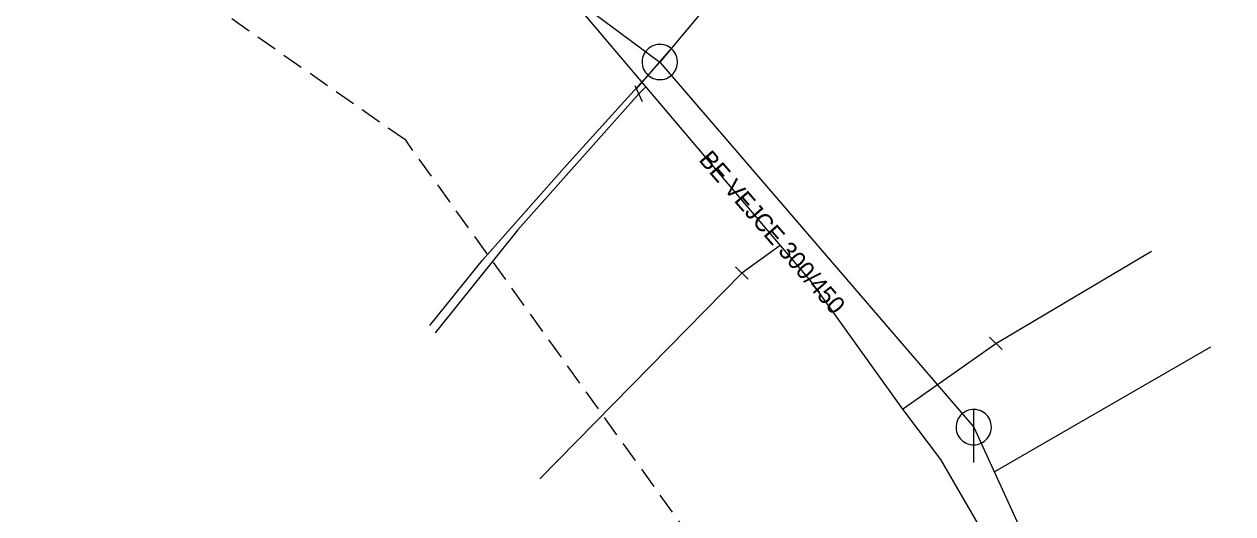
# Model space of a CAD drawing. Extents: x -749365 to -748625, y -965388 to -964881.
# Drawn here: x -748769.4 to -748701, y -965299.8 to -965272.1 of the extents above; entities that cross this region are included whole.
import ezdxf

# ---------------------------------------------------------------- set-up
doc = ezdxf.new("R2010")
doc.units = 0
doc.header["$LTSCALE"] = 0.4
doc.linetypes.add('MEDIUM_DASHED', pattern=[4.5, 3, -1.5])
for name, color, linetype, lineweight in [('1', 7, 'MEDIUM_DASHED', 25), ('11', 7, 'Continuous', 13), ('13', 7, 'Continuous', 13), ('14', 7, 'Continuous', 13), ('17', 7, 'Continuous', 25), ('22', 7, 'Continuous', 13), ('34', 7, 'Continuous', 13)]:
    doc.layers.add(name, color=color, linetype=linetype, lineweight=lineweight)

msp = doc.modelspace()

# ---------------------------------------------------------------- linework, layer by layer
at = {"layer": '1'}
msp.add_lwpolyline([(-748672.881, -965383.055), (-748747.771, -965278.626), (-748913.896, -965162.751)], dxfattribs=at)
at = {"layer": '11'}
for p, q in [((-748713.426, -965250.271), (-748733.398, -965274.196)), ((-748702.245, -965290.34), (-748714.473, -965297.398))]:
    msp.add_line(p, q, dxfattribs=at)
msp.add_lwpolyline([(-748746.413, -965289.099), (-748743.425, -965285.418), (-748738.662, -965280.008), (-748733.398, -965274.196)], dxfattribs=at)
at = {"layer": '13'}
for p, q in [((-748726.585, -965284.577), (-748728.763, -965286.143)), ((-748714.396, -965290.12), (-748705.592, -965284.897)), ((-748728.763, -965286.143), (-748740.183, -965297.786)), ((-748719.677, -965293.835), (-748714.396, -965290.12))]:
    msp.add_line(p, q, dxfattribs=at)
msp.add_lwpolyline([(-748734.588, -965275.991), (-748741.421, -965283.688), (-748746.104, -965289.53)], dxfattribs=at)
at = {"layer": '14', "lineweight": 25}
for p, q in [((-748733.398, -965274.196), (-748715.64, -965294.859)), ((-748715.64, -965294.859), (-748702.52, -965323.41))]:
    msp.add_line(p, q, dxfattribs=at)
at = {"layer": '14'}
msp.add_line((-748734.193, -965275.594), (-748734.588, -965275.991), dxfattribs=at)
at = {"layer": '14', "lineweight": 25}
msp.add_lwpolyline([(-748815.416, -965213.761), (-748783.169, -965237.598), (-748775.37, -965243.07), (-748733.398, -965274.196)], dxfattribs=at)
at = {"layer": '17'}
msp.add_lwpolyline([(-748738.234, -965270.822), (-748726.585, -965284.577), (-748724.84, -965286.638), (-748719.677, -965293.835), (-748717.51, -965296.688), (-748705.515, -965317.423), (-748697.278, -965331.659), (-748689.392, -965346.28), (-748687.454, -965349.21), (-748674.822, -965372.635), (-748674.485, -965375.898)], dxfattribs=at)
at = {"layer": '22'}
for p, q in [((-748734.708, -965275.707), (-748732.743, -965273.44)), ((-748715.64, -965296.859), (-748715.639, -965293.859))]:
    msp.add_line(p, q, dxfattribs=at)
for points in [[(-748732.642, -965274.851), (-748732.576, -965274.765), (-748732.518, -965274.671), (-748732.472, -965274.572), (-748732.436, -965274.469), (-748732.411, -965274.362), (-748732.399, -965274.253), (-748732.399, -965274.143), (-748732.411, -965274.035), (-748732.434, -965273.928), (-748732.469, -965273.824), (-748732.515, -965273.725), (-748732.573, -965273.631), (-748732.639, -965273.544), (-748732.715, -965273.465), (-748732.8, -965273.395), (-748732.89, -965273.335), (-748732.988, -965273.283), (-748733.09, -965273.244), (-748733.196, -965273.217), (-748733.303, -965273.2), (-748733.414, -965273.196), (-748733.522, -965273.204), (-748733.631, -965273.224), (-748733.735, -965273.254), (-748733.836, -965273.297), (-748733.931, -965273.35), (-748734.021, -965273.414), (-748734.102, -965273.487), (-748734.176, -965273.568), (-748734.24, -965273.657), (-748734.294, -965273.752), (-748734.337, -965273.853), (-748734.369, -965273.957), (-748734.39, -965274.065), (-748734.397, -965274.175), (-748734.394, -965274.284), (-748734.378, -965274.392), (-748734.351, -965274.498), (-748734.313, -965274.6), (-748734.262, -965274.698), (-748734.203, -965274.79), (-748734.133, -965274.874), (-748734.054, -965274.951), (-748733.968, -965275.018), (-748733.874, -965275.075), (-748733.776, -965275.122), (-748733.672, -965275.157), (-748733.565, -965275.182), (-748733.456, -965275.194), (-748733.347, -965275.195), (-748733.238, -965275.183), (-748733.131, -965275.159), (-748733.027, -965275.125), (-748732.928, -965275.078), (-748732.834, -965275.022), (-748732.747, -965274.955), (-748732.668, -965274.879)], [(-748714.64, -965294.859), (-748714.645, -965294.75), (-748714.663, -965294.642), (-748714.693, -965294.536), (-748714.733, -965294.435), (-748714.785, -965294.338), (-748714.847, -965294.248), (-748714.919, -965294.165), (-748714.999, -965294.091), (-748715.087, -965294.025), (-748715.181, -965293.97), (-748715.281, -965293.925), (-748715.386, -965293.892), (-748715.493, -965293.87), (-748715.602, -965293.86), (-748715.712, -965293.862), (-748715.82, -965293.876), (-748715.927, -965293.901), (-748716.03, -965293.938), (-748716.128, -965293.987), (-748716.22, -965294.045), (-748716.306, -965294.114), (-748716.383, -965294.191), (-748716.452, -965294.277), (-748716.511, -965294.369), (-748716.559, -965294.467), (-748716.596, -965294.57), (-748716.622, -965294.677), (-748716.636, -965294.785), (-748716.639, -965294.895), (-748716.629, -965295.004), (-748716.608, -965295.111), (-748716.574, -965295.215), (-748716.53, -965295.315), (-748716.475, -965295.41), (-748716.409, -965295.498), (-748716.335, -965295.578), (-748716.252, -965295.65), (-748716.162, -965295.712), (-748716.066, -965295.764), (-748715.964, -965295.805), (-748715.859, -965295.835), (-748715.751, -965295.853), (-748715.641, -965295.859), (-748715.532, -965295.853), (-748715.424, -965295.835), (-748715.319, -965295.806), (-748715.217, -965295.765), (-748715.12, -965295.713), (-748715.03, -965295.651), (-748714.947, -965295.58), (-748714.872, -965295.5), (-748714.807, -965295.412), (-748714.751, -965295.318), (-748714.707, -965295.218), (-748714.673, -965295.114), (-748714.651, -965295.006), (-748714.641, -965294.897)]]:
    msp.add_lwpolyline(points, close=True, dxfattribs=at)
at = {"layer": '34'}
for p, q in [((-748734.374, -965276.443), (-748734.8, -965275.538)), ((-748729.12, -965285.793), (-748728.406, -965286.493)), ((-748714.753, -965289.77), (-748714.039, -965290.47))]:
    msp.add_line(p, q, dxfattribs=at)

# ---------------------------------------------------------------- texts
at = {"layer": '1'}
msp.add_text('BE VEJCE 300/450', height=1, rotation=311, dxfattribs=at).set_placement((-748731.238, -965279.754))

doc.saveas('drawing.dxf')
